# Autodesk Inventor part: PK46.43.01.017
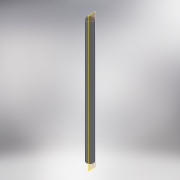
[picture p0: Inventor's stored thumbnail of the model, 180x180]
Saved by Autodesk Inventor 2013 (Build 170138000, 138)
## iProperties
Shininess: 64.0
Length Units: 11269
Angle Units: 11279
Time Units: 11290
Mass Units: 11283
Length Display Precision: 3
Angle Display Precision: 2
Compacted: True
Part Number: PK46.43.01.017
Document SubType Name: Modeling
Created: 2004-12
Material: Сталь высокопрочная низколегированная
Designer: ELarisa
Manufacturer: Standard
Standards Organization: Custom
Density: 7.84 g/cm^3
Density: 0.0
Volumn: 0.0
Area: 0.0
PropertySet Name: Model Information
Control State: 0
Master: False
Checked Out: False
Checked Out Date: 2008-10-09
Last Check In Date: 2008-10-09
Author: ELarisa
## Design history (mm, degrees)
sketch "Эскиз1"
  geometry: C1 r 10 at (-7.57, 2.54); C2 r 12.5 at (-7.57, 2.54)
  constraints: 2 centre point, 1 coincident
  dimensions: "d0" = 25 diameter of C2; "d1" = 20 diameter of C1
extrude "Выдавливание2" new body sketch "Эскиз1" distance "d10" = 440; taper "d11" = 0 deg
body "Solid1"
